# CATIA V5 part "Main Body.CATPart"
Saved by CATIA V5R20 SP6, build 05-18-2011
Part number: Main Body
Bounding box of the stored display mesh (mm): x 0 to 30, y -30.013 to 69, z -34 to 36.998
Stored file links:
  E:\#03 University\#02 영남 이공대\#01 2021\#02 여름 방학\#01 Documents\K-Move Page02 ASD02\Main Body.CATPart

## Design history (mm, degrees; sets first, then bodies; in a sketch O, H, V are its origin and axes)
Set1 "Reference Data"
  Point1 "Center Point": (0, 0, 0)
  Plane1 "Plane.1(Y Dir=69mm)": type Offset, RefPlane zx-plane, Offset 69
  Plane2 "Plane.2(Z Dir=-34mm": type Offset, RefPlane xy-plane, Offset 34, reversed
Body1 (main body)
  Body2 "Main Body"
    Sketch1 on yz-plane, origin (0, 0, 0), H (0, 1, 0), V (0, 0, 1)
      arc A1 centre (0, 0) radius 23 from (0, -23) to (-20.4003, 10.6221) ccw
      construction circle A2 centre (0, 0) radius 30
      arc A3 centre (0, 0) radius 37 from (31.1288, 20) to (-31.9296, 18.695) ccw
      construction line L1 (0, 0) -> (-30.3086, 21.2223)
      point P1 (-30.3086, 21.2223)
      construction line L2 (0, 0) -> (37, 0)
      point P2 (37, 0)
      line L3 (-20.4003, 10.6221) -> (-31.9296, 18.695)
      point P3 (-1.7207, -2.4575)
      point P4 (-32.0294, 18.7649)
      construction line L4 (0, 0) -> (-1.7207, -2.4575)
      construction line L5 (-30.3086, 21.2223) -> (-32.0294, 18.7649)
      line L6 (31.1288, 20) -> (69, 20)
      line L7 (69, 20) -> (69, -34)
      line L8 (69, -34) -> (0, -34)
      point P7 (0, -34)
      line L9 (0, -34) -> (0, -23)
      arc A4 centre (0, 0) radius 34 from (34, 0) to (-27.8512, 19.5016) ccw
      arc A5 centre (0, 0) radius 26 from (26, 0) to (-21.298, 14.913) ccw
      line L10 (26, 0) -> (34, 0)
      point P12 (26, 0)
      line L11 (-21.298, 14.913) -> (-27.8512, 19.5016)
      point P13 (-21.298, 14.913)
      reference intersected line E1 through (69, 0) direction (0, 1) from Plane1
      reference intersected line E2 through (0, -34) direction (-1, 0) from Plane2
      radius A1 = 23
      radius A2 = 30
      radius A3 = 37
      angle V L1 = 55
      distance L1 L3 = 3
      distance L8 L6 = 54
      distance A2 A4 = 4
      distance A2 A5 = 4
      coincidence: P1 A3, P2 A3, P7 V, P3 L3, P4 L3, P12 A5, P12 L2, P13 A5, P13 L1, P13 L11, P12 L10, L7 E1, L8 E2
      horizontal: L2 H, L6 H, L8 H, L10 H
      perpendicularity: L4 L1, L4 L3, L5 L1, L5 L3
      vertical: L7 V, L9 V
      concentricity: A2 A4, A2 A5
      parallelism: L11 L1
    Pad1: profile Sketch1, direction (1, 0, 0), length 10
    Fillet1: radius 10, on edge [face of Pad1 from Sketch1.L6 | face of Pad1 from Sketch1.L7]; edge [face of Pad1 from Sketch1.A3 | face of Pad1 from Sketch1.L6]
    Fillet2: radius 2, on edge [face of Pad1 from Sketch1.A4 | face of Pad1 from Sketch1.L11]; edge [face of Pad1 from Sketch1.L11 | face of Pad1 from Sketch1.A5]; edge [face of Pad1 from Sketch1.A5 | face of Pad1 from Sketch1.L10]; edge [face of Pad1 from Sketch1.L10 | face of Pad1 from Sketch1.A4]
    Fillet3: radius 5, on edge [face of Pad1 from Sketch1.L3 | face of Pad1 from Sketch1.A3]; edge [face of Pad1 from Sketch1.A1 | face of Pad1 from Sketch1.L3]
  Assemble1: tool Body2
  Body3 "Base Body"
    Sketch2 on yz-plane, origin (0, 0, 0), H (0, 1, 0), V (0, 0, 1)
      point P1 (0, -29)
      line L1 (0, -29) -> (69, -29)
      line L2 (69, -29) -> (69, -34)
      line L3 (69, -34) -> (0, -34)
      line L4 (0, -34) -> (0, -29)
      reference intersected line E1 through (69, 0) direction (0, 1) from Plane1
      reference intersected line E2 through (0, -34) direction (-1, 0) from Plane2
      distance L3 L1 = 5
      coincidence: P1 V, L2 E1, L3 E2
      horizontal: L1 H, L3 H
      vertical: L2 V, L4 V
    Pad2: profile Sketch2, direction (1, 0, 0), length 30
  Assemble2: tool Body3
  Fillet4: radius 5, on edge [end face of Pad1 | face of Pad2 from Sketch2.L1]
  Body4 "Hole Body"
    Body5 "Hole Body(D8)"
      Sketch3 on yz-plane, origin (0, 0, 0), H (0, 1, 0), V (0, 0, 1)
        circle A1 centre (48, -1) radius 4
        point P1 (48, -1)
        reference intersected line E1 through (0, -34) direction (-1, 0) from Plane2
        distance P1 V = 48
        distance E1 P1 = 33
        radius A1 = 4
      Pad3: profile Sketch3, direction (1, 0, 0), length 30
    Assemble3: tool Body5
    Body6 "Hole Body(D7)"
      Sketch4 on Plane2, origin (0, 0, -34), H (0, 1, 0), V (-1, 0, 0)
        circle A1 centre (13, -20) radius 3.5
        point P1 (13, -20)
        distance V P1 = 13
        distance H P1 = 20
        radius A1 = 3.5
      Pad4: profile Sketch4, direction (0, 0, 1), length 30
      RectPattern1: of the body so far, direction 1 instances 2, spacing 43, along edge [face of Pad2 from Sketch2.L1 | end face of Pad2] reversed
    Assemble4: tool Body6
  Remove1: tool Body4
